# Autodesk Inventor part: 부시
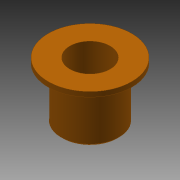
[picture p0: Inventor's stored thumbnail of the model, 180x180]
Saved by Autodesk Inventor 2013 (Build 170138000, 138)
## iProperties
Created: 2015-10
Part Number: 부시
Document SubType Name: Modeling
Designer: mdu
Density: 7.86 g/cm^3
Material: 황동, 연질
Mass: 246.97 g
Surface Area: 129.264 cm^2
Volume: 31.4212 cm^3
Author: mdu
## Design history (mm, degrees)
sketch "스케치1"
  geometry: C1 r 31 at (0, 0) reference; C2 r 25 at (0, 0) reference; C3 r 30 at (0, 0) reference; C4 r 26 at (0, 0); C5 r 18 at (0, 0); 1 further point
  constraints: 2 centre point, 2 coincident
  dimensions: "d20" = 5 radial gap between concentric circles of C1 C4; "d21" = 8 radial gap between concentric circles of C5 C4
  node "참조1"
  node "참조2"
  node "참조4"
extrude "돌출1" new body sketch "스케치1" distance "d0" = 10; taper "d1" = 0 deg
extrude "돌출2" join sketch "스케치1" distance "d2" = 35; taper "d3" = 0 deg
sketch "스케치4"
  geometry: C1 r 12.5 at (0, 0); 1 further point
  constraints: 1 centre point, 1 coincident
  dimensions: "d24" = 25 diameter of C1
extrude "돌출5" cut sketch "스케치4" stored distance "d25" = 10; taper "d26" = 0 deg
chamfer "모따기1" distance "d6" = 1; stored, may be unused: second distance "d7" = 2, angle "d8" = 45 deg
node "솔리드1"
